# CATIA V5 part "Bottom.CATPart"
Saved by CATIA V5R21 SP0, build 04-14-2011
Part number: Plate
Bounding box of the stored display mesh (mm): x -85 to 85, y -84.802 to 84.802, z 0 to 10
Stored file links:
  D:\CATIA V5R21 E-RESOURCES\CATIA-V5R21\catia-v5r21-prt\c12-catia-v5r20-prt\c12-catia-v5-r20-figr-12-30\cat_v5r21_Bottom.CATPart
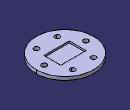
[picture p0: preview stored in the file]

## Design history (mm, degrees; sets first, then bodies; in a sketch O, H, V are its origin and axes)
Body1 (main body)
  Sketch1 on xy-plane, origin (0, 0, 0), H (1, 0, 0), V (0, 1, 0)
    circle A1 centre (0, 0) radius 85
    line L1 (37.5, 25) -> (37.5, -25)
    line L2 (37.5, -25) -> (-37.5, -25)
    line L3 (-37.5, -25) -> (-37.5, 25)
    line L4 (-37.5, 25) -> (37.5, 25)
    length L2 = 75
    length L1 = 50
    radius A1 = 85
    vertical: L1 V, L3 V
    horizontal: L2 H, L4 H
    equidistance: L1 L3 O, L2 L4 O
  MultiPad1: profile Sketch1, domains (length 5; length 10)
  Sketch2 on face of MultiPad1, origin (0, 0, 10), H (1, 0, 0), V (0, 1, 0)
    circle A1 centre (62, 0) radius 7.5
    point P1 (62, 0)
    radius A1 = 7.5
    distance P1 V = 62
    coincidence: P1 H
  Pocket1: profile Sketch2, direction (0, 0, -1), through (limit type 6)
  CircPattern1: of Pocket1, instances 6, angular step 60 {= 360.0*1 deg/CircPattern1.AngularNumber}, axis from xy-plane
